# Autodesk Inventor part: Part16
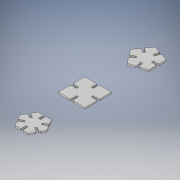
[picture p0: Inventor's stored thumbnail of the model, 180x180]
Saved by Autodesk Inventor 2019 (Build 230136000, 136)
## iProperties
Created: 2019-02
Part Number: Part16
Material: Generic
Document SubType Name: Modeling
Designer: aramy
Density: 1 g/cm^3
Appearance: Default
Author: aramy
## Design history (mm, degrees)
sketch "Sketch3"
  geometry: L1 (-23.793, -72.827)-(26.207, -122.827); L2 (26.207, -72.827)-(-23.793, -122.827); L3 (103.194, 107.296)-(103.194, 103.496); L4 (103.194, 71.125)-(103.194, 61.125); L5 (10.966, 4.335)-(18.569, 8.724); L6 (16.669, 12.015)-(9.066, 7.625); L7 (9.066, 7.625)-(10.966, 4.335); L8 (10.966, 4.335)-(17.726, 12.625); L9 (19.626, 9.335)-(9.066, 7.625); L10 (12.5, 21.651)-(16.995, 13.865); L11 (20.334, 8.082)-(25, 0); L12 (16.995, 13.865)-(16.669, 12.015); L13 (16.995, 13.865)-(18.874, 13.865); L14 (14.346, 8.48)-(15.29, 9.025); L15 (20.334, 8.082)-(18.569, 8.724); L16 (1.729, 11.664)-(-2.071, 21.664); L17 (-2.071, 20.443)-(-2.071, 11.664); L18 (-3.51, 21.651)-(-2.571, 23.278); L19 (-3.51, 21.651)-(-2.071, 20.443); L20 (-2.071, 11.664)-(1.729, 11.664); L21 (-0.171, 16.664)-(-0.171, 17.754); L22 (1.729, 11.664)-(1.729, 20.443); L23 (1.729, 21.664)-(-2.071, 11.664); L24 (3.168, 21.651)-(1.729, 20.443); L25 (-9.237, 7.329)-(-19.797, 9.038); L26 (-18.74, 8.428)-(-11.137, 4.038); L27 (-20.505, 7.786)-(-21.444, 9.412); L28 (-20.505, 7.786)-(-18.74, 8.428); L29 (-11.137, 4.038)-(-9.237, 7.329); L30 (-14.517, 8.184)-(-15.461, 8.729); L31 (-9.237, 7.329)-(-16.84, 11.719); L32 (-17.897, 12.329)-(-11.137, 4.038); L33 (-17.166, 13.569)-(-16.84, 11.719); L34 (-10.966, -4.335)-(-17.726, -12.625); L35 (-16.669, -12.015)-(-9.066, -7.625); L36 (-16.995, -13.865)-(-18.874, -13.865); L37 (-16.995, -13.865)-(-16.669, -12.015); L38 (-9.066, -7.625)-(-10.966, -4.335); L39 (-14.346, -8.48)-(-15.29, -9.025); L40 (-10.966, -4.335)-(-18.569, -8.724); L41 (-19.626, -9.335)-(-9.066, -7.625); L42 (-20.334, -8.082)-(-18.569, -8.724); L43 (-1.729, -11.664)-(2.071, -21.664); L44 (2.071, -20.443)-(2.071, -11.664); L45 (3.51, -21.651)-(2.571, -23.278); L46 (3.51, -21.651)-(2.071, -20.443); L47 (2.071, -11.664)-(-1.729, -11.664); L48 (0.171, -16.664)-(0.171, -17.754); L49 (-1.729, -11.664)-(-1.729, -20.443); L50 (-1.729, -21.664)-(2.071, -11.664); L51 (-3.168, -21.651)-(-1.729, -20.443); L52 (9.237, -7.329)-(19.797, -9.038); L53 (18.74, -8.428)-(11.137, -4.038); L54 (20.505, -7.786)-(21.444, -9.412); L55 (20.505, -7.786)-(18.74, -8.428); L56 (11.137, -4.038)-(9.237, -7.329); L57 (14.517, -8.184)-(15.461, -8.729); L58 (9.237, -7.329)-(16.84, -11.719); L59 (17.897, -12.329)-(11.137, -4.038); L60 (17.166, -13.569)-(16.84, -11.719); L61 (25, 0)-(20.505, -7.786); L62 (17.166, -13.569)-(12.5, -21.651); L63 (12.5, -21.651)-(3.51, -21.651); L64 (-3.168, -21.651)-(-12.5, -21.651)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; 21 further points
  constraints: 364 end point, 35 midpoint, 20 point on line, 7 symmetric about line, 4 horizontal, 4 parallel, 3 coincident, 3 perpendicular, 3 vertical, 2 collinear, 1 equal length, 361 other
  dimensions: "d18" = 50 distance of L1.end L2.end (= d21); "d19" = 50 distance of L2.start L1.end (= d21); "d21" = 50 distance of L66.end L11.end; "d23" = 3.8 distance of L3.start L3.end; "d24" = 10 distance of L4.start L4.end; "d27" = 10 distance of L5.start L9.start (= d24); "d28" = 3.8 distance of L6.end L5.start (= d23); "d30" = 100 deg angle of L12 L13; "d33" = 360 deg dimension on point (0, 0) L5.start (derived); "d35" = 10 distance of L75.end L72.end (= d24); "d36" = 3.8 distance of L72.end L71.end (= d23); "d38" = 1.20753 distance from line of L6.start L10; "d39" = 1.43908 distance from line of L10.end L6; "d42" = 1.43908 vertical distance of L71.start L76.end (derived); "d43" = 140 deg angle of L76 L78 (derived); "d44" = 140 deg angle of L12 L10; "d47" = 360 deg dimension on point (1.207, -97.827) L74.start (derived); "d49" = 3.8 distance of L115.end L114.start (derived); "d50" = 10 distance of L114.start L111.end (derived); "d54" = 360 deg dimension on point (0, -210.304) L114.start (derived); "d58" = 3.8 distance of L162.end L163.end (derived); "d59" = 10 distance of L166.start L162.end (derived); "d60" = 28.9135 distance of point (6.684, 193.385) L167.start; "d63" = 360 deg dimension on point (0, 178) L162.end (derived)
extrude "Extrusion1" new body sketch "Sketch3" distance "d65" = 3; taper "d66" = 0 deg
body "Solid1"
